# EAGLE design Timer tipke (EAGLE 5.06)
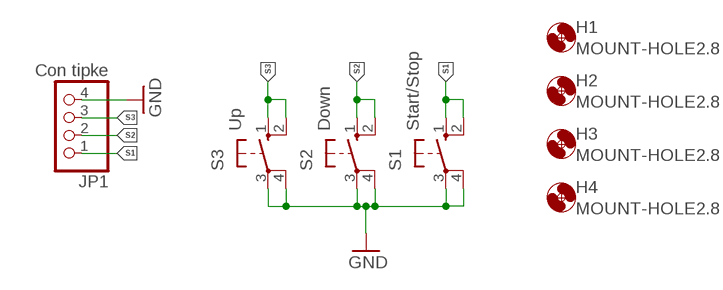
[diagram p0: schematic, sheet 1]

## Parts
H1  MOUNT-HOLE2.8  [2,8]
H2  MOUNT-HOLE2.8  [2,8]
H3  MOUNT-HOLE2.8  [2,8]
H4  MOUNT-HOLE2.8  [2,8]
JP1  Con tipke  PINHD-1X4  [1X04]
S1  Start/Stop  10-XX  [B3F-10XX]
S2  Down  10-XX  [B3F-10XX]
S3  Up  10-XX  [B3F-10XX]

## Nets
GND: JP1.4 S1.3(P) S1.4(P1) S2.3(P) S2.4(P1) S3.3(P) S3.4(P1)
S1: JP1.1 S1.1(S) S1.2(S1)
S2: JP1.2 S2.1(S) S2.2(S1)
S3: JP1.3 S3.1(S) S3.2(S1)

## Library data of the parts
H1-H4 = holes:MOUNT-HOLE: MOUNTING HOLE with drill center marker
JP1 = pinhead:PINHD-1X4: PIN HEADER
S1-S3 = switch-omron:10-XX: OMRON SWITCH

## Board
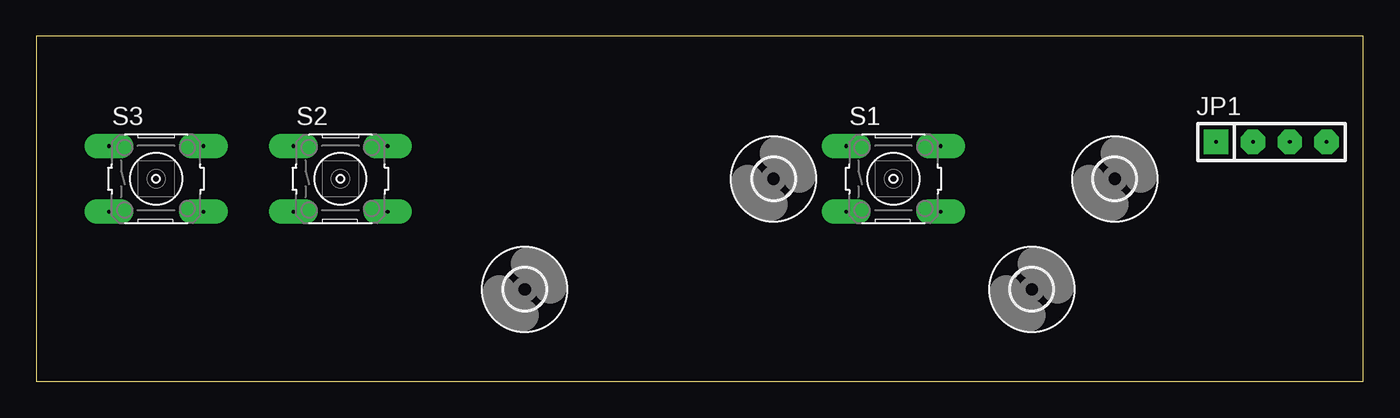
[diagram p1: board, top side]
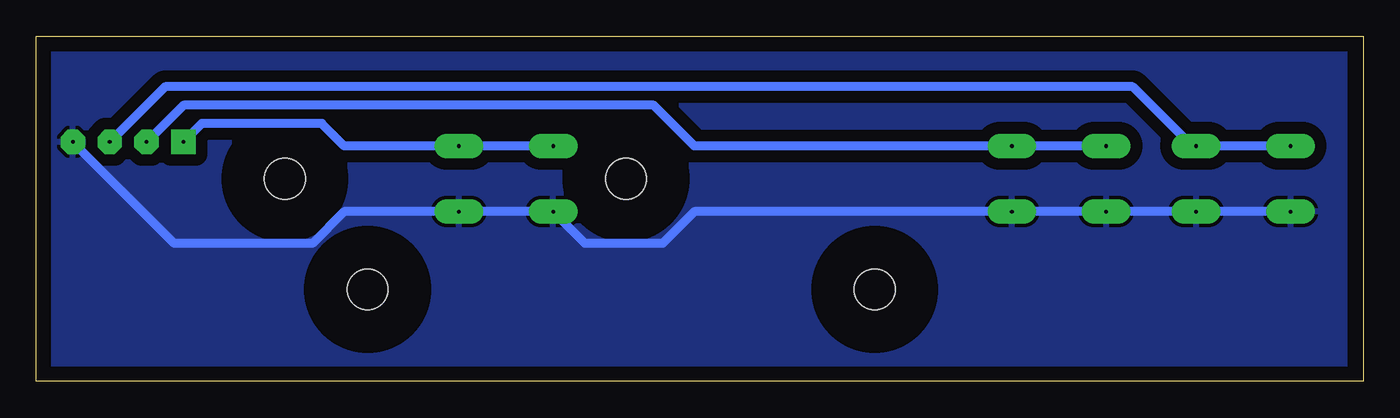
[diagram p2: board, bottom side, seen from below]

Size 91.42 x 23.8 mm. Coordinates in mm from the lower left corner, seen from the top.
Outline: 0,0 91.42,0 91.42,23.8 0,23.8 0,0
Copper layers (1*16): Top 0.035mm / dielectric 1.5mm / Bottom 0.035mm
Design rules "default *": minimum track width 16mil, minimum drill 1mil, track to track 8mil, track to pad 8mil, pad to pad 8mil, via to via 8mil, smd to smd 8mil, copper to edge 40mil, drill to drill 1mil, minimum pad ring 10mil, minimum via ring 8mil, stop-mask expansion 4mil, vias tented up to drill 0mil, thermal gap 10mil

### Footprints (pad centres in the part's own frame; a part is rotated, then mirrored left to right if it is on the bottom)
2,8 = hole 2.8: 0,0
1X04 = drill 0.254 pad 1.676 square: 1 -3.81,0 | drill 0.254 pad 1.676 octagon: 2 -1.27,0; 3 1.27,0; 4 3.81,0
B3F-10XX = drill 0.254 pad 1.676 long: 1 -3.251,2.261; 2 3.251,2.261; 3 -3.251,-2.261; 4 3.251,-2.261

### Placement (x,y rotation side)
H1  68.58,6.35 0 top
H2  74.29,13.97 0 top
H3  50.8,13.97 0 top
H4  33.66,6.35 0 top
JP1  85.09,16.51 0 top
S1  59.05,13.97 0 top
S2  20.95,13.97 0 top
S3  8.26,13.97 0 top

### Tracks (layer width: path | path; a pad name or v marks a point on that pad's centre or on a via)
GND
  Bottom 0.61: S3.4 S3.3 S2.3 S2.4 46.08,11.71 48.26,9.53 53.62,9.53 S1.3 S1.4 70.21,11.71 72.39,9.53 81.91,9.53 JP1.4
  pour Bottom (isolate 0.813): 1.27,0.64 1.27,22.86 92.07,22.86 92.07,0.64
S1
  Bottom 0.61: S1.1 S1.2 70.21,16.23 71.75,17.78 80.01,17.78 JP1.1
S2
  Bottom 0.61: S2.1 S2.2 46.08,16.23 48.9,19.05 81.28,19.05 JP1.2
S3
  Bottom 0.61: S3.1 S3.2 11.79,16.23 15.88,20.32 82.55,20.32 JP1.3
